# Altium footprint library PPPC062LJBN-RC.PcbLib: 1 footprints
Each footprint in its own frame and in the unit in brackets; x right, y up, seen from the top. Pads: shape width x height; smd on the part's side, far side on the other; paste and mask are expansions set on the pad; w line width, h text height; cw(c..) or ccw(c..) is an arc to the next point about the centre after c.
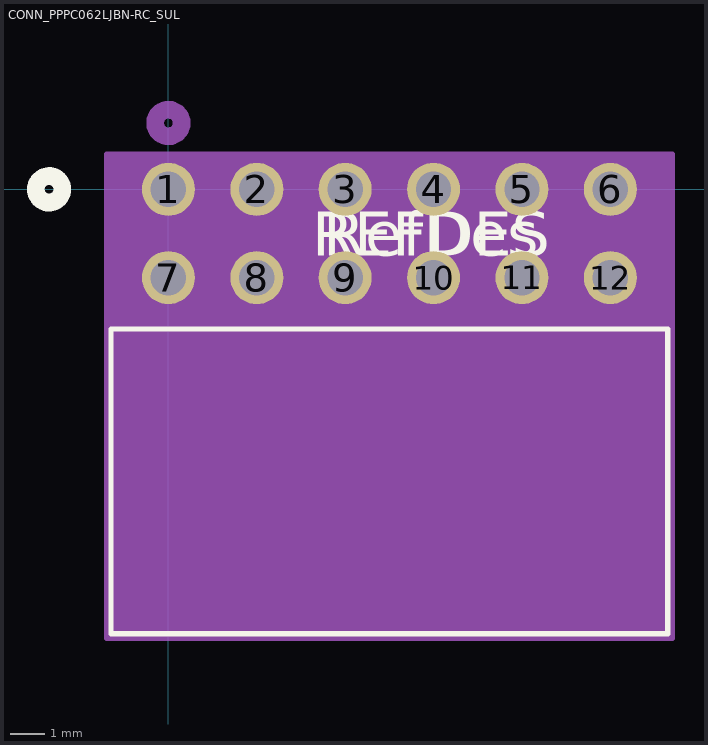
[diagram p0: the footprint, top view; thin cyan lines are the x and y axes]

## CONN_PPPC062LJBN-RC_SUL [mil]
pads (12):
  round 60 hole 40 paste-30 mask+0: 1(0,0) 2(100,0) 3(200,0) 4(300,0) 5(400,0) 6(500,0) 7(0,-100) 8(100,-100) 9(200,-100) 10(300,-100) 11(400,-100) 12(500,-100)
Top Overlay:
  circle w20: c-135,0 r15
  lines w6: -65,-502.99 565,-502.99 565,-157.99 -65,-157.99 -65,-502.99
  text "RefDes" at 175,-75 h50
  text "REFDES" at 162.5,-75 h50
Bottom Overlay:
  circle w20: c-135,0 r15
Mechanical 13:
  circle w20: c0,75 r15
  lines w1: -60,-497.99 560,-497.99 560,-162.99 -60,-162.99 -60,-497.99
  text "RefDes2" at 162.5,-75 h50
Mechanical 15:
  region: 570,40 -70,40 -70,-507.99 570,-507.99
  lines w6: -70,-507.99 -70,40 570,40 570,-507.99 -70,-507.99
